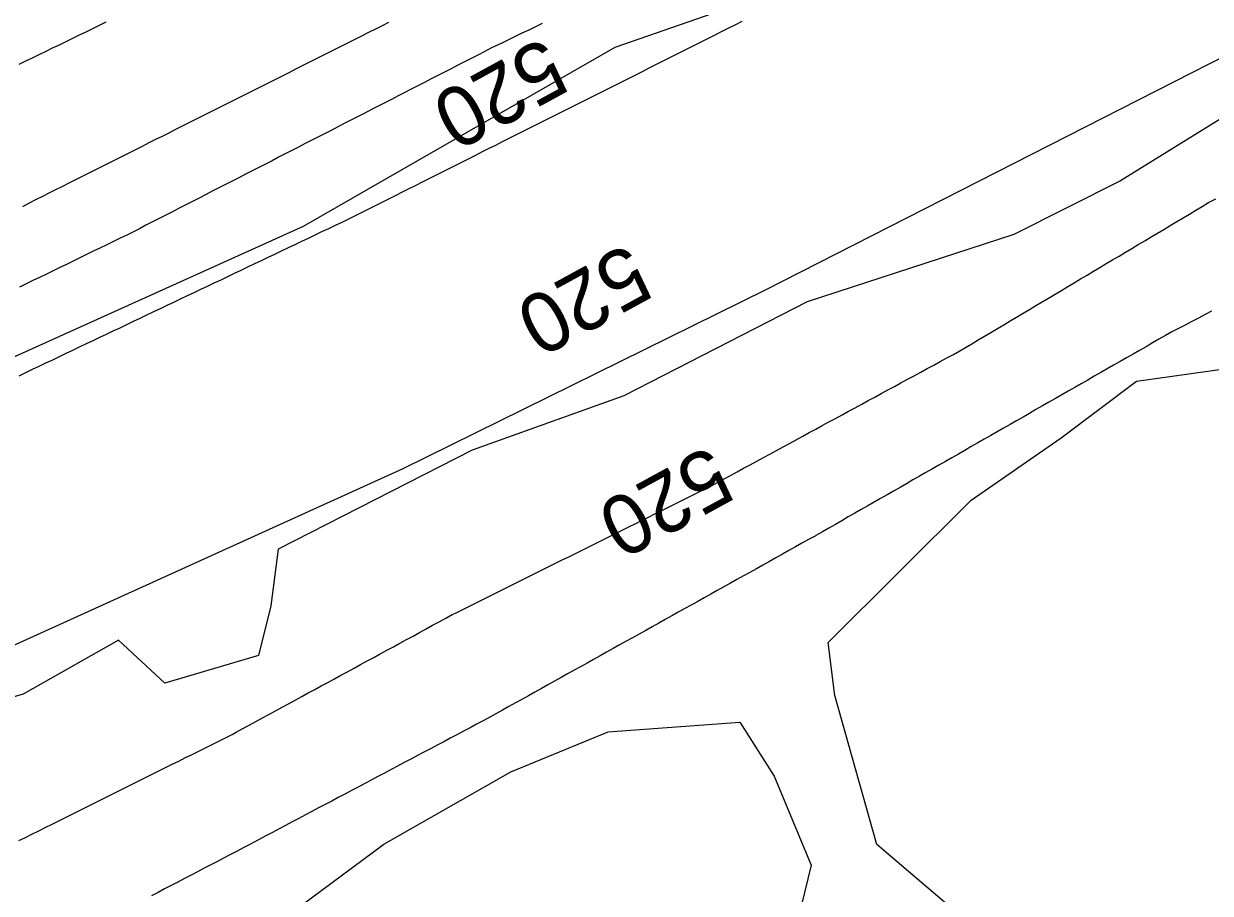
# Model space of a CAD drawing. Extents: x 1901471 to 1963503, y 756461 to 799997.
# Drawn here: x 1928420.2 to 1928579.4, y 772351.8 to 772468.4 of the extents above; entities that cross this region are included whole.
import ezdxf

# ---------------------------------------------------------------- set-up
doc = ezdxf.new("R2010")
doc.units = 0
for name, color, linetype in [('RD_EX_Fence_Other', 7, 'Continuous'), ('RD_EX_H2O', 7, 'Continuous'), ('RD_EX_Road', 7, 'Continuous'), ('RD_EX_VEG', 7, 'Continuous'), ('RD_HC_Cl', 7, 'Continuous'), ('RD_HC_TX_Sta50', 7, 'Continuous')]:
    doc.layers.add(name, color=color, linetype=linetype)

msp = doc.modelspace()

# ---------------------------------------------------------------- linework, layer by layer
at = {"layer": 'RD_EX_Fence_Other'}
msp.add_lwpolyline([(1928895.27, 772596.98), (1928834.61, 772577.29), (1928778.94, 772557.41), (1928733.95, 772539.37), (1928689.79, 772519.2), (1928595.92, 772471.51), (1928519.66, 772432.64), (1928471.08, 772408.71), (1928397.76, 772375.45), (1928284.7, 772325.12), (1928290.51, 772300.92), (1928299.59, 772264.01), (1928266.54, 772247.26), (1928155.59, 772193.61), (1928053.03, 772134.41), (1927953.68, 772074.71)], dxfattribs=at)
at = {"layer": 'RD_EX_H2O'}
msp.add_lwpolyline([(1928419.61, 772421.18), (1928420.52, 772421.61), (1928421.42, 772422.04), (1928422.32, 772422.47), (1928423.22, 772422.9), (1928424.13, 772423.33), (1928425.03, 772423.76), (1928425.93, 772424.19), (1928426.84, 772424.62), (1928427.74, 772425.05), (1928428.64, 772425.48), (1928429.54, 772425.9), (1928430.45, 772426.33), (1928431.35, 772426.76), (1928432.25, 772427.19), (1928433.16, 772427.62), (1928434.06, 772428.05), (1928434.96, 772428.48), (1928435.87, 772428.91), (1928436.77, 772429.34), (1928437.67, 772429.77), (1928438.57, 772430.2), (1928439.48, 772430.63), (1928440.38, 772431.06), (1928441.28, 772431.49), (1928442.19, 772431.92), (1928443.09, 772432.34), (1928443.99, 772432.77), (1928444.89, 772433.2), (1928445.8, 772433.63), (1928446.7, 772434.06), (1928447.6, 772434.49), (1928448.51, 772434.92), (1928449.41, 772435.35), (1928450.31, 772435.78), (1928451.22, 772436.21), (1928452.12, 772436.64), (1928453.02, 772437.07), (1928453.92, 772437.5), (1928454.83, 772437.93), (1928455.73, 772438.36), (1928456.63, 772438.78), (1928457.54, 772439.21), (1928458.44, 772439.64), (1928459.34, 772440.07), (1928460.24, 772440.5), (1928461.15, 772440.93), (1928462.05, 772441.36), (1928462.95, 772441.79), (1928463.92, 772442.25), (1928464.81, 772442.7), (1928465.7, 772443.15), (1928466.6, 772443.6), (1928467.49, 772444.04), (1928468.38, 772444.49), (1928469.28, 772444.94), (1928470.17, 772445.39), (1928471.06, 772445.84), (1928471.95, 772446.29), (1928472.85, 772446.74), (1928473.74, 772447.19), (1928474.63, 772447.64), (1928475.53, 772448.08), (1928476.42, 772448.53), (1928476.42, 772448.53), (1928477.31, 772448.98), (1928478.21, 772449.43), (1928479.1, 772449.88), (1928479.99, 772450.33), (1928480.89, 772450.78), (1928481.78, 772451.23), (1928482.67, 772451.68), (1928483.57, 772452.12), (1928484.46, 772452.57), (1928485.35, 772453.02), (1928486.24, 772453.47), (1928487.14, 772453.92), (1928488.03, 772454.37), (1928488.92, 772454.82), (1928489.82, 772455.27), (1928490.71, 772455.72), (1928491.6, 772456.16), (1928492.5, 772456.61), (1928493.39, 772457.06), (1928494.28, 772457.51), (1928495.18, 772457.96), (1928496.07, 772458.41), (1928496.96, 772458.86), (1928497.86, 772459.31), (1928498.75, 772459.75), (1928499.64, 772460.2), (1928500.53, 772460.65), (1928501.43, 772461.1), (1928502.32, 772461.55), (1928503.21, 772462), (1928504.11, 772462.45), (1928505, 772462.9), (1928505.89, 772463.35), (1928506.79, 772463.79), (1928507.68, 772464.24), (1928508.57, 772464.69), (1928509.47, 772465.14), (1928510.36, 772465.59), (1928511.25, 772466.04), (1928512.15, 772466.49), (1928513.04, 772466.94), (1928513.93, 772467.39), (1928514.82, 772467.83), (1928515.72, 772468.28), (1928516.61, 772468.73)], dxfattribs=at)
at = {"layer": 'RD_EX_Road'}
for points in [[(1928419.63, 772462.95), (1928420.53, 772463.39), (1928421.43, 772463.82), (1928422.33, 772464.26), (1928423.23, 772464.7), (1928424.12, 772465.13), (1928425.02, 772465.57), (1928425.92, 772466.01), (1928426.82, 772466.44), (1928427.72, 772466.88), (1928428.62, 772467.32), (1928429.52, 772467.75), (1928430.42, 772468.19), (1928431.32, 772468.63)], [(1928469.18, 772468.56), (1928468.29, 772468.11), (1928467.4, 772467.66), (1928466.5, 772467.22), (1928465.61, 772466.77), (1928464.72, 772466.32), (1928463.82, 772465.87), (1928462.93, 772465.42), (1928462.04, 772464.97), (1928461.14, 772464.52), (1928460.25, 772464.07), (1928459.36, 772463.62), (1928458.46, 772463.17), (1928457.57, 772462.72), (1928456.68, 772462.27), (1928455.78, 772461.82), (1928454.89, 772461.37), (1928454, 772460.92), (1928453.11, 772460.47), (1928452.21, 772460.03), (1928451.32, 772459.58), (1928450.43, 772459.13), (1928449.53, 772458.68), (1928448.64, 772458.23), (1928447.75, 772457.78), (1928446.85, 772457.33), (1928445.96, 772456.88), (1928445.07, 772456.43), (1928444.17, 772455.98), (1928443.28, 772455.53), (1928442.39, 772455.08), (1928441.49, 772454.63), (1928440.6, 772454.18), (1928439.71, 772453.73), (1928438.81, 772453.28), (1928437.92, 772452.84), (1928437.03, 772452.39), (1928436.13, 772451.94), (1928435.24, 772451.49), (1928434.35, 772451.04), (1928433.45, 772450.59), (1928432.56, 772450.14), (1928431.67, 772449.69), (1928430.78, 772449.24), (1928429.88, 772448.79), (1928428.99, 772448.34), (1928428.1, 772447.89), (1928427.2, 772447.44), (1928426.31, 772446.99), (1928425.42, 772446.54), (1928424.52, 772446.1), (1928423.63, 772445.65), (1928422.74, 772445.2), (1928421.84, 772444.75), (1928420.95, 772444.3), (1928420.06, 772443.85)], [(1928489.76, 772468.41), (1928488.86, 772467.97), (1928487.96, 772467.54), (1928487.06, 772467.1), (1928486.16, 772466.67), (1928485.26, 772466.23), (1928484.36, 772465.8), (1928483.46, 772465.36), (1928482.9, 772465.09), (1928482.01, 772464.63), (1928481.12, 772464.18), (1928480.23, 772463.72), (1928479.34, 772463.26), (1928478.45, 772462.81), (1928477.56, 772462.35), (1928476.67, 772461.89), (1928475.78, 772461.44), (1928474.89, 772460.98), (1928474, 772460.52), (1928473.11, 772460.07), (1928472.22, 772459.61), (1928471.33, 772459.15), (1928470.44, 772458.7), (1928469.55, 772458.24), (1928468.66, 772457.78), (1928467.77, 772457.33), (1928466.88, 772456.87), (1928465.99, 772456.41), (1928465.1, 772455.96), (1928464.21, 772455.5), (1928463.32, 772455.04), (1928462.44, 772454.59), (1928461.55, 772454.13), (1928460.66, 772453.68), (1928459.77, 772453.22), (1928458.88, 772452.76), (1928457.99, 772452.31), (1928457.1, 772451.85), (1928456.21, 772451.39), (1928455.32, 772450.94), (1928454.43, 772450.48), (1928453.54, 772450.02), (1928452.65, 772449.57), (1928451.76, 772449.11), (1928450.87, 772448.65), (1928449.98, 772448.2), (1928449.09, 772447.74), (1928448.2, 772447.28), (1928447.31, 772446.83), (1928446.42, 772446.37), (1928445.53, 772445.91), (1928444.64, 772445.46), (1928443.75, 772445), (1928442.86, 772444.54), (1928441.98, 772444.09), (1928441.09, 772443.63), (1928440.2, 772443.17), (1928439.31, 772442.72), (1928438.42, 772442.26), (1928437.53, 772441.8), (1928436.64, 772441.35), (1928435.75, 772440.89), (1928434.97, 772440.49), (1928434.07, 772440.05), (1928433.17, 772439.62), (1928432.27, 772439.18), (1928431.37, 772438.74), (1928430.47, 772438.3), (1928429.57, 772437.87), (1928428.68, 772437.43), (1928427.78, 772436.99), (1928426.88, 772436.55), (1928425.98, 772436.11), (1928425.08, 772435.68), (1928424.18, 772435.24), (1928423.28, 772434.8), (1928422.38, 772434.36), (1928421.48, 772433.93), (1928420.59, 772433.49), (1928419.69, 772433.05)], [(1928419.57, 772358.83), (1928420.46, 772359.27), (1928421.35, 772359.72), (1928422.25, 772360.16), (1928423.14, 772360.61), (1928424.04, 772361.05), (1928424.93, 772361.5), (1928425.83, 772361.94), (1928426.72, 772362.39), (1928427.62, 772362.83), (1928428.51, 772363.28), (1928429.41, 772363.72), (1928430.3, 772364.17), (1928431.2, 772364.61), (1928432.09, 772365.06), (1928432.98, 772365.51), (1928433.88, 772365.95), (1928434.77, 772366.4), (1928435.67, 772366.84), (1928436.56, 772367.29), (1928437.46, 772367.73), (1928438.35, 772368.18), (1928439.25, 772368.62), (1928440.14, 772369.07), (1928441.04, 772369.51), (1928441.93, 772369.96), (1928442.83, 772370.4), (1928442.83, 772370.4), (1928443.72, 772370.85), (1928444.62, 772371.29), (1928445.51, 772371.74), (1928446.4, 772372.18), (1928447.3, 772372.63), (1928448.19, 772373.07), (1928448.74, 772373.37), (1928449.61, 772373.85), (1928450.49, 772374.32), (1928451.37, 772374.8), (1928452.25, 772375.28), (1928453.13, 772375.76), (1928454.01, 772376.24), (1928454.88, 772376.71), (1928455.76, 772377.19), (1928456.64, 772377.67), (1928457.52, 772378.15), (1928458.4, 772378.63), (1928459.28, 772379.1), (1928460.15, 772379.58), (1928461.03, 772380.06), (1928461.91, 772380.54), (1928462.79, 772381.02), (1928463.67, 772381.49), (1928464.55, 772381.97), (1928465.42, 772382.45), (1928466.3, 772382.93), (1928467.18, 772383.41), (1928468.06, 772383.88), (1928468.94, 772384.36), (1928469.81, 772384.84), (1928470.69, 772385.32), (1928471.57, 772385.8), (1928472.45, 772386.27), (1928473.33, 772386.75), (1928474.21, 772387.23), (1928475.08, 772387.71), (1928475.96, 772388.19), (1928476.84, 772388.66), (1928477.72, 772389.14), (1928478.13, 772389.34), (1928479.02, 772389.79), (1928479.92, 772390.24), (1928480.81, 772390.68), (1928481.71, 772391.13), (1928482.61, 772391.57), (1928483.5, 772392.02), (1928484.4, 772392.46), (1928485.29, 772392.91), (1928486.19, 772393.35), (1928487.08, 772393.8), (1928487.98, 772394.24), (1928488.87, 772394.69), (1928489.77, 772395.13), (1928490.66, 772395.58), (1928491.56, 772396.02), (1928492.46, 772396.47), (1928493.35, 772396.91), (1928494.25, 772397.36), (1928495.14, 772397.8), (1928496.04, 772398.25), (1928496.93, 772398.69), (1928497.83, 772399.14), (1928498.72, 772399.58), (1928498.72, 772399.58), (1928499.62, 772400.03), (1928500.51, 772400.47), (1928501.41, 772400.92), (1928502.31, 772401.36), (1928503.2, 772401.81), (1928504.1, 772402.25), (1928504.99, 772402.7), (1928505.89, 772403.14), (1928506.78, 772403.59), (1928507.68, 772404.03), (1928508.57, 772404.48), (1928509.47, 772404.93), (1928510.36, 772405.37), (1928511.26, 772405.82), (1928512.16, 772406.26), (1928512.4, 772406.39), (1928513.28, 772406.87), (1928514.16, 772407.35), (1928515.04, 772407.82), (1928515.92, 772408.3), (1928516.79, 772408.78), (1928517.67, 772409.25), (1928518.55, 772409.73), (1928519.43, 772410.21), (1928520.31, 772410.68), (1928521.19, 772411.16), (1928522.07, 772411.64), (1928522.95, 772412.11), (1928523.83, 772412.59), (1928524.71, 772413.07), (1928525.58, 772413.55), (1928526.46, 772414.02), (1928527.34, 772414.5), (1928528.22, 772414.98), (1928529.1, 772415.45), (1928529.98, 772415.93), (1928530.86, 772416.41), (1928531.74, 772416.88), (1928532.62, 772417.36), (1928533.49, 772417.84), (1928534.37, 772418.31), (1928535.25, 772418.79), (1928536.13, 772419.27), (1928537.01, 772419.74), (1928537.89, 772420.22), (1928538.77, 772420.7), (1928539.65, 772421.17), (1928540.53, 772421.65), (1928541.41, 772422.13), (1928542.28, 772422.6), (1928543.16, 772423.08), (1928544.04, 772423.56), (1928544.92, 772424.04), (1928545.8, 772424.51), (1928546.53, 772424.95), (1928547.39, 772425.46), (1928548.25, 772425.97), (1928549.11, 772426.48), (1928549.96, 772426.99), (1928550.82, 772427.51), (1928551.68, 772428.02), (1928552.54, 772428.53), (1928553.4, 772429.04), (1928554.26, 772429.55), (1928554.26, 772429.55), (1928555.11, 772430.07), (1928555.97, 772430.58), (1928556.83, 772431.09), (1928557.69, 772431.6), (1928558.55, 772432.11), (1928559.41, 772432.62), (1928560.27, 772433.14), (1928561.12, 772433.65), (1928561.98, 772434.16), (1928562.84, 772434.67), (1928563.7, 772435.18), (1928564.56, 772435.7), (1928565.42, 772436.21), (1928566.27, 772436.72), (1928567.13, 772437.23), (1928567.99, 772437.74), (1928568.85, 772438.25), (1928569.71, 772438.77), (1928570.57, 772439.28), (1928571.43, 772439.79), (1928572.28, 772440.3), (1928573.14, 772440.81), (1928574, 772441.33), (1928574.86, 772441.84), (1928575.72, 772442.35), (1928576.58, 772442.86), (1928577.43, 772443.37), (1928578.29, 772443.88), (1928579.15, 772444.4), (1928580.1, 772444.89)], [(1928579.55, 772429.83), (1928578.67, 772429.37), (1928577.78, 772428.91), (1928576.89, 772428.45), (1928576.01, 772427.98), (1928575.12, 772427.52), (1928574.22, 772427.05), (1928573.35, 772426.56), (1928572.48, 772426.06), (1928571.62, 772425.57), (1928570.75, 772425.07), (1928569.88, 772424.57), (1928569.01, 772424.08), (1928568.14, 772423.58), (1928567.28, 772423.08), (1928566.41, 772422.59), (1928565.54, 772422.09), (1928564.67, 772421.59), (1928563.8, 772421.1), (1928562.94, 772420.6), (1928562.07, 772420.11), (1928561.2, 772419.61), (1928560.33, 772419.11), (1928559.47, 772418.62), (1928558.6, 772418.12), (1928558.6, 772418.12), (1928557.73, 772417.62), (1928556.86, 772417.13), (1928555.99, 772416.63), (1928555.13, 772416.13), (1928554.26, 772415.64), (1928553.39, 772415.14), (1928552.52, 772414.65), (1928551.65, 772414.15), (1928550.79, 772413.65), (1928549.92, 772413.16), (1928549.05, 772412.66), (1928548.18, 772412.16), (1928547.31, 772411.67), (1928546.45, 772411.17), (1928545.58, 772410.67), (1928544.71, 772410.18), (1928543.84, 772409.68), (1928542.97, 772409.19), (1928542.11, 772408.69), (1928541.24, 772408.19), (1928540.37, 772407.7), (1928539.5, 772407.2), (1928538.64, 772406.7), (1928537.77, 772406.21), (1928536.9, 772405.71), (1928536.03, 772405.21), (1928535.16, 772404.72), (1928534.3, 772404.22), (1928533.43, 772403.73), (1928532.56, 772403.23), (1928531.69, 772402.73), (1928530.82, 772402.24), (1928529.96, 772401.74), (1928529.09, 772401.24), (1928528.22, 772400.75), (1928527.35, 772400.25), (1928526.48, 772399.75), (1928526.36, 772399.68), (1928525.49, 772399.2), (1928524.61, 772398.71), (1928523.74, 772398.22), (1928522.87, 772397.74), (1928521.99, 772397.25), (1928521.12, 772396.76), (1928520.25, 772396.27), (1928519.37, 772395.79), (1928518.5, 772395.3), (1928517.63, 772394.81), (1928516.75, 772394.33), (1928515.88, 772393.84), (1928515.01, 772393.35), (1928514.13, 772392.87), (1928513.26, 772392.38), (1928512.39, 772391.89), (1928511.51, 772391.41), (1928510.64, 772390.92), (1928509.77, 772390.43), (1928508.89, 772389.95), (1928508.02, 772389.46), (1928507.14, 772388.97), (1928506.27, 772388.49), (1928505.4, 772388), (1928504.52, 772387.51), (1928503.65, 772387.02), (1928503.65, 772387.02), (1928502.78, 772386.54), (1928501.9, 772386.05), (1928501.03, 772385.56), (1928500.16, 772385.08), (1928499.28, 772384.59), (1928498.41, 772384.1), (1928497.54, 772383.62), (1928496.66, 772383.13), (1928495.79, 772382.64), (1928494.92, 772382.16), (1928494.04, 772381.67), (1928493.17, 772381.18), (1928492.3, 772380.7), (1928491.42, 772380.21), (1928490.55, 772379.72), (1928489.68, 772379.24), (1928488.8, 772378.75), (1928487.93, 772378.26), (1928487.06, 772377.78), (1928486.18, 772377.29), (1928485.31, 772376.8), (1928484.44, 772376.31), (1928483.56, 772375.83), (1928482.75, 772375.37), (1928481.87, 772374.91), (1928480.98, 772374.44), (1928480.1, 772373.97), (1928479.22, 772373.5), (1928478.33, 772373.03), (1928477.45, 772372.57), (1928476.57, 772372.1), (1928475.68, 772371.63), (1928474.8, 772371.16), (1928473.92, 772370.69), (1928473.03, 772370.23), (1928472.15, 772369.76), (1928471.27, 772369.29), (1928470.38, 772368.82), (1928469.5, 772368.35), (1928468.62, 772367.89), (1928467.73, 772367.42), (1928466.85, 772366.95), (1928465.97, 772366.48), (1928465.08, 772366.01), (1928464.2, 772365.55), (1928463.32, 772365.08), (1928462.43, 772364.61), (1928461.55, 772364.14), (1928460.67, 772363.67), (1928459.78, 772363.21), (1928458.9, 772362.74), (1928458.02, 772362.27), (1928457.13, 772361.8), (1928456.25, 772361.33), (1928455.37, 772360.87), (1928454.48, 772360.4), (1928453.6, 772359.93), (1928452.72, 772359.46), (1928451.83, 772358.99), (1928450.95, 772358.53), (1928450.65, 772358.37), (1928449.76, 772357.9), (1928448.88, 772357.44), (1928447.99, 772356.98), (1928447.99, 772356.98), (1928447.11, 772356.51), (1928446.22, 772356.05), (1928445.33, 772355.59), (1928444.45, 772355.13), (1928443.56, 772354.66), (1928442.68, 772354.2), (1928441.79, 772353.74), (1928440.9, 772353.27), (1928440.02, 772352.81), (1928439.13, 772352.35), (1928438.25, 772351.89), (1928437.36, 772351.42)]]:
    msp.add_lwpolyline(points, dxfattribs=at)
at = {"layer": 'RD_EX_VEG'}
for points in [[(1928327.88, 772345.87), (1928325.4, 772355.55), (1928325.39, 772370.52), (1928330.96, 772378.45), (1928351.76, 772391.49), (1928397.91, 772414.22), (1928457.78, 772441.22), (1928499.54, 772465.22), (1928529.18, 772475.59), (1928566.62, 772493.18), (1928592.33, 772499.26)], [(1928581.64, 772456.17), (1928567.32, 772447.31), (1928553.01, 772440.12), (1928525.31, 772431.07), (1928500.72, 772418.47), (1928480.38, 772411.2), (1928454.37, 772397.93), (1928453.37, 772390.3), (1928451.72, 772383.65), (1928439.15, 772379.97), (1928432.96, 772385.73), (1928420.18, 772378.49), (1928401.45, 772373.02), (1928385.92, 772367.5), (1928369.31, 772352.52), (1928350.98, 772345.98)], [(1928544.34, 772350.02), (1928534.67, 772358.29), (1928529.02, 772378.31), (1928528.11, 772385.39), (1928547.3, 772404.49), (1928559.38, 772412.83), (1928569.46, 772420.44), (1928587.01, 772422.91)], [(1928456.05, 772349.11), (1928468.55, 772358.36), (1928485.58, 772368.05), (1928498.6, 772373.41), (1928516.27, 772374.72), (1928520.88, 772367.48), (1928525.85, 772355.53), (1928522.74, 772342.9)]]:
    msp.add_lwpolyline(points, dxfattribs=at)
at = {"layer": 'RD_HC_Cl'}
for centre, radius, start, end in [((1933934.02, 762479.74), 11482.38, 112.01316, 122.84589), ((1933920.67, 762509.14), 11420.5, 112.014247, 122.846378), ((1933910.03, 762523.4), 11373.86, 112.013249, 123.541888)]:
    msp.add_arc(centre, radius, start, end, dxfattribs=at)

# ---------------------------------------------------------------- texts
at = {"layer": 'RD_HC_TX_Sta50'}
for rotation, p in [(208.639, (1928490.07, 772466.73)), (208.6681, (1928501.33, 772439.08)), (208.6726, (1928512.28, 772411.98))]:
    msp.add_text('520', height=8, rotation=rotation, dxfattribs=at).set_placement(p)

doc.saveas('drawing.dxf')
